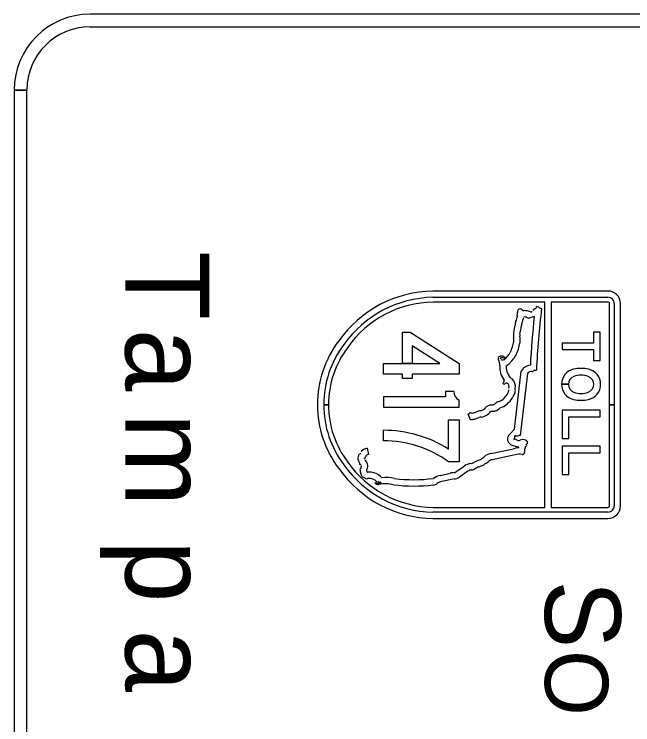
# Model space of a CAD drawing. Extents: x -830008.4 to -829992.7, y 1290284.1 to 1290294.4.
# Drawn here: x -830004.537 to -830004.047, y 1290288.025 to 1290288.587 of the extents above; entities that cross this region are included whole.
import ezdxf

# ---------------------------------------------------------------- set-up
doc = ezdxf.new("R2010")
doc.units = 0
doc.layers.add('SheetBorder_dp', color=7, linetype='Continuous')

msp = doc.modelspace()

# ---------------------------------------------------------------- linework, layer by layer
at = {"layer": 'SheetBorder_dp'}
for p, q in [((-830003.816909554, 1290288.587291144), (-830004.476909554, 1290288.587291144)), ((-830004.476909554, 1290288.577291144), (-830003.816909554, 1290288.577291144)), ((-830004.536909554, 1290288.527291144), (-830004.526909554, 1290288.527291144)), ((-830004.536909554, 1290288.527191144), (-830004.536909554, 1290287.717291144)), ((-830004.526909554, 1290288.5271911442), (-830004.536909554, 1290288.527191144)), ((-830004.526909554, 1290287.717291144), (-830004.526909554, 1290288.5271911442)), ((-830004.0981922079, 1290288.2943725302), (-830004.1035956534, 1290288.2943725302)), ((-830004.1035956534, 1290288.29437103), (-830004.0981922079, 1290288.29437103)), ((-830004.2446846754, 1290288.2497011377), (-830004.2446846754, 1290288.2579751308)), ((-830004.1930847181, 1290288.2430990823), (-830004.1930847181, 1290288.2430990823))]:
    msp.add_line(p, q, dxfattribs=at)
for points in [[(-830004.0669087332, 1290288.3682224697), (-830004.2054374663, 1290288.3682224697)], [(-830004.205393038, 1290288.3632224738), (-830004.0669087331, 1290288.3632224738)], [(-830004.2053588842, 1290288.1969726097), (-830004.1169086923, 1290288.1969726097), (-830004.1169086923, 1290288.3594724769), (-830004.2053588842, 1290288.3594724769)], [(-830004.0669087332, 1290288.3594724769), (-830004.1119086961, 1290288.3594724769), (-830004.1119086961, 1290288.19697261), (-830004.0669087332, 1290288.19697261)], [(-830004.0619087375, 1290288.3582224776), (-830004.0619087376, 1290288.2782225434), (-830004.0656587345, 1290288.2782225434), (-830004.0656587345, 1290288.3582224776)], [(-830004.0569087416, 1290288.198222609), (-830004.0569087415, 1290288.3582224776)], [(-830004.1261738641, 1290288.3530989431), (-830004.1257116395, 1290288.3532741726)], [(-830004.1387743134, 1290288.34870282), (-830004.138744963, 1290288.348874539)], [(-830004.1385513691, 1290288.348487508), (-830004.1387164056, 1290288.3485801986)], [(-830004.125191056, 1290288.3481242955), (-830004.1291381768, 1290288.346627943)], [(-830004.1448537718, 1290288.2546439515), (-830004.1408525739, 1290288.2590014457), (-830004.1355260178, 1290288.3048247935)], [(-830004.1307013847, 1290288.3030265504), (-830004.136407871, 1290288.2539347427)], [(-830004.188884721, 1290288.2886301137), (-830004.195484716, 1290288.2886301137), (-830004.1954847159, 1290288.2844931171)], [(-830004.1954847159, 1290288.2844931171), (-830004.2446846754, 1290288.2844931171), (-830004.2446846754, 1290288.2762191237), (-830004.1846847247, 1290288.276219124), (-830004.1846847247, 1290288.281833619)], [(-830004.2881585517, 1290288.2782225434), (-830004.2919085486, 1290288.2782225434)], [(-830004.2919085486, 1290288.2782205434), (-830004.2881585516, 1290288.2782205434)], [(-830004.2919085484, 1290288.2782205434), (-830004.2919085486, 1290288.2782205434)], [(-830004.0656587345, 1290288.1982226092), (-830004.0656587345, 1290288.2782205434), (-830004.0619087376, 1290288.2782205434), (-830004.0619087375, 1290288.198222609)], [(-830004.1930847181, 1290288.2430990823), (-830004.1930847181, 1290288.2661687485), (-830004.1846847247, 1290288.2661687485), (-830004.1846847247, 1290288.2330727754), (-830004.1930847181, 1290288.2330727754)], [(-830004.1757909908, 1290288.2661882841), (-830004.1775703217, 1290288.2708609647)], [(-830004.1409836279, 1290288.251466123), (-830004.141267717, 1290288.2511567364)], [(-830004.2575626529, 1290288.24375316), (-830004.2565490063, 1290288.2388569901)], [(-830004.1595911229, 1290288.2396098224), (-830004.14163251, 1290288.2434177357)], [(-830004.137820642, 1290288.2440571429), (-830004.1375218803, 1290288.2449362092)], [(-830004.1324797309, 1290288.2442337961), (-830004.1330139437, 1290288.2426619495)], [(-830004.1404133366, 1290288.2385650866), (-830004.1586556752, 1290288.2346970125)], [(-830004.174686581, 1290288.2317725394), (-830004.1711591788, 1290288.2336529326)], [(-830004.1872336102, 1290288.2250885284), (-830004.1807183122, 1290288.2295878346)], [(-830004.1692456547, 1290288.2290069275), (-830004.1725016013, 1290288.2272712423)], [(-830004.259800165, 1290288.2204873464), (-830004.2609410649, 1290288.2208415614)], [(-830004.1994168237, 1290288.2223282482), (-830004.1919079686, 1290288.2240285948)], [(-830004.1776866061, 1290288.2256050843), (-830004.1844265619, 1290288.220950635)], [(-830004.1907742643, 1290288.2191587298), (-830004.1985112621, 1290288.2174067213)], [(-830004.0669087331, 1290288.193222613), (-830004.205393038, 1290288.193222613)], [(-830004.2054374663, 1290288.1882226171), (-830004.0669087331, 1290288.1882226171)]]:
    msp.add_lwpolyline(points, dxfattribs=at)
for points in [[(-830004.2296432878, 1290288.335617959), (-830004.2234668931, 1290288.335617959), (-830004.1846847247, 1290288.310795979), (-830004.1846847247, 1290288.3025219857), (-830004.221843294, 1290288.302521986), (-830004.221843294, 1290288.2989759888), (-830004.2296432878, 1290288.2989759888), (-830004.2296432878, 1290288.3025219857), (-830004.2446846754, 1290288.3025219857), (-830004.2446846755, 1290288.310795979), (-830004.2001014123, 1290288.310795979), (-830004.221843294, 1290288.3247113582), (-830004.2218432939, 1290288.310798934), (-830004.2296432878, 1290288.310798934)], [(-830004.0784087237, 1290288.3356224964), (-830004.0784087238, 1290288.3270725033), (-830004.1031587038, 1290288.3270725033), (-830004.1031587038, 1290288.3218225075), (-830004.0784087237, 1290288.3218225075), (-830004.0784087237, 1290288.3132725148), (-830004.0731587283, 1290288.3132725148), (-830004.0731587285, 1290288.3356224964)], [(-830004.1031587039, 1290288.2516225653), (-830004.0979087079, 1290288.2516225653), (-830004.0979087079, 1290288.2687225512), (-830004.0731587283, 1290288.2687225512), (-830004.0731587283, 1290288.273972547), (-830004.1031587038, 1290288.273972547)], [(-830004.1031587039, 1290288.2229725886), (-830004.0979087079, 1290288.2229725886), (-830004.0979087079, 1290288.2400725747), (-830004.0731587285, 1290288.2400725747), (-830004.0731587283, 1290288.2453225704), (-830004.1031587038, 1290288.2453225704)]]:
    msp.add_lwpolyline(points, close=True, dxfattribs=at)
for centre, radius, start, end in [((-830004.476909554, 1290288.527291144), 0.05999999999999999, 90.00000000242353, 180.00000000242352), ((-830004.476909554, 1290288.527291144), 0.05000000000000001, 90.00000000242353, 180.00000000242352), ((-830004.2038046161, 1290288.275081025), 0.09315575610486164, 91.00434193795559, 144.7824347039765), ((-830004.0669087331, 1290288.3582224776), 0.009999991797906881, 2.423533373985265e-09, 90.00000000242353), ((-830004.2038046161, 1290288.275081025), 0.08815576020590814, 91.03243189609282, 144.83740042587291), ((-830004.0669087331, 1290288.3582224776), 0.004999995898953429, 2.4235191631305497e-09, 90.00000000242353), ((-830004.2038046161, 1290288.275081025), 0.08440576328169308, 91.0551178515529, 144.883032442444), ((-830004.1240072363, 1290288.3554398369), 0.0005142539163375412, 298.4069525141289, 10.835103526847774), ((-830004.1231717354, 1290288.3556065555), 0.0003377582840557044, 75.52908349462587, 191.96938409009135), ((-830004.150207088, 1290288.2872858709), 0.07381051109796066, 67.16009206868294, 68.44316308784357), ((-830004.0669087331, 1290288.3582224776), 0.0012499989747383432, 2.4230217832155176e-09, 90.00000000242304), ((-830004.1494486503, 1290288.3514472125), 0.011008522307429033, 346.4850910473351, 358.21970391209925), ((-830004.1327886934, 1290288.3513882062), 0.0056638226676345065, 163.2595638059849, 182.86400577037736), ((-830004.136357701, 1290288.351879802), 0.0021770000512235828, 39.09543145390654, 148.42860737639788), ((-830004.1337250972, 1290288.3538688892), 0.0011265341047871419, 213.16301982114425, 279.1931240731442), ((-830004.134058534, 1290288.334774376), 0.017989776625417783, 69.2674504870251, 88.3645978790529), ((-830004.1275632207, 1290288.352184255), 0.0005986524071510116, 257.7695425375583, 302.1923495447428), ((-830004.1279048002, 1290288.3528732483), 0.0013659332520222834, 298.91861737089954, 349.1899173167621), ((-830004.1260337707, 1290288.352587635), 0.0005301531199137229, 105.32244340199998, 176.8180848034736), ((-830004.1257972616, 1290288.3536258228), 0.00036192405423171, 283.6844802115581, 22.75102928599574), ((-830004.1252127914, 1290288.3538480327), 0.0002638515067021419, 104.46933041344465, 198.16203331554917), ((-830004.1291469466, 1290288.3624800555), 0.009226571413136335, 294.78716688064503, 305.70207615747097), ((-830003.550934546, 1290288.2820833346), 0.5730414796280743, 172.74340527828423, 177.64053368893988), ((-830004.118862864, 1290288.3590295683), 0.004593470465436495, 234.090301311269, 263.45802429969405), ((-830004.0454778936, 1290288.3126107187), 0.09965940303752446, 158.96382008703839, 161.50316928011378), ((-830004.1386791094, 1290288.348672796), 9.9826512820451e-05, 162.496701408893, 248.06130225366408), ((-830004.1385744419, 1290288.3484081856), 8.261021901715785e-05, 343.1200005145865, 73.7815449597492), ((-830004.0454778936, 1290288.3126107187), 0.09465940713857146, 158.9395609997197, 161.3538881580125), ((-830004.1385744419, 1290288.3484081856), 0.005082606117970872, 339.48312628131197, 352.50601186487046), ((-830004.1337250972, 1290288.3538688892), 0.006126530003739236, 271.7757633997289, 272.7092640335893), ((-830004.134058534, 1290288.334774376), 0.01298978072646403, 77.51121985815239, 87.25088211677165), ((-830004.1279048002, 1290288.3528732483), 0.0063659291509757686, 238.30424406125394, 258.8284940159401), ((-830003.550934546, 1290288.2820833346), 0.5780414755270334, 173.43965958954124, 177.2795063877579), ((-830004.2198288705, 1290288.352123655), 0.08016743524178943, 347.9815123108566, 352.25032233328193), ((-830004.1247112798, 1290288.340621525), 0.015697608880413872, 166.71827368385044, 177.47368236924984), ((-830004.2131072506, 1290288.3510964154), 0.0783691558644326, 347.42098246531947, 352.51703163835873), ((-830004.1247112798, 1290288.340621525), 0.010697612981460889, 167.8371768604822, 178.56038546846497), ((-830004.133587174, 1290288.333143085), 0.008158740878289, 163.71730815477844, 193.3081791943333), ((-830004.133587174, 1290288.333143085), 0.0031587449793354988, 163.71730815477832, 194.09444291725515), ((-830004.2131586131, 1290288.2782225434), 0.08374993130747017, 142.84750742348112, 179.9993266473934), ((-830004.1497002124, 1290288.3295572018), 0.008349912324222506, 344.30322825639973, 11.802168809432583), ((-830004.1497002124, 1290288.3295572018), 0.01334990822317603, 345.2933259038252, 12.180223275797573), ((-830004.2131586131, 1290288.2782225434), 0.0787499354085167, 142.78617292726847, 180.00000000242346), ((-830004.2131586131, 1290288.2782225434), 0.07499993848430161, 142.73495458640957, 180.00000000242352), ((-830004.169564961, 1290288.3326148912), 0.02840527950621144, 330.4722802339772, 349.2120997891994), ((-830004.169564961, 1290288.3326148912), 0.03340527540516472, 330.1681482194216, 348.87275100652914), ((-830004.1530039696, 1290288.3153763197), 0.000901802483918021, 108.32673284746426, 189.0854984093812), ((-830004.1511357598, 1290288.3121874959), 0.004581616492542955, 57.31174888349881, 118.0117489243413), ((-830004.1566254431, 1290288.3264806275), 0.01416135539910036, 312.410764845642, 326.26217754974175), ((-830004.1383939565, 1290288.3178459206), 0.015719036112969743, 189.56510050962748, 202.43401243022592), ((-830004.1564028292, 1290288.3100726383), 0.00390587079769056, 349.75666267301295, 27.02253734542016), ((-830004.1514036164, 1290288.3146474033), 0.0006510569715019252, 120.7488524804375, 235.01068498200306), ((-830004.1502268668, 1290288.3180414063), 0.004222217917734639, 248.461594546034, 274.2264195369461), ((-830004.1505274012, 1290288.3115154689), 0.0038844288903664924, 74.6263603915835, 108.13545261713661), ((-830004.1496703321, 1290288.3154151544), 0.0016033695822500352, 261.19737803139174, 323.4243709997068), ((-830004.149169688, 1290288.3158976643), 0.0007162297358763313, 242.75361409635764, 336.469149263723), ((-830004.1486821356, 1290288.3157949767), 0.0002493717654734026, 312.70176638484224, 85.22491620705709), ((-830004.1334120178, 1290288.303275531), 0.018687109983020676, 136.97994108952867, 143.23758320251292), ((-830004.1503473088, 1290288.3160387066), 0.0075193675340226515, 291.67644084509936, 322.5951392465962), ((-830004.1334120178, 1290288.303275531), 0.01368711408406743, 137.6878246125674, 143.2173430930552), ((-830004.1566254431, 1290288.3264806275), 0.019161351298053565, 313.09802819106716, 326.8309060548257), ((-830004.1352930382, 1290288.308246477), 0.017303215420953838, 176.25033295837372, 217.78592799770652), ((-830004.1352930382, 1290288.308246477), 0.012303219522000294, 176.2503329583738, 217.7859279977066), ((-830004.127333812, 1290288.3001287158), 0.009442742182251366, 96.02257115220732, 150.17705715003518), ((-830004.1268230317, 1290288.3057072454), 0.0011761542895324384, 256.0840041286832, 320.7997150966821), ((-830004.1244722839, 1290288.3029491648), 0.002476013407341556, 89.3658460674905, 125.54177339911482), ((-830004.1244963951, 1290288.3075714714), 0.002147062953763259, 271.37486247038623, 297.9457993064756), ((-830004.0915219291, 1290288.29454494), 0.012074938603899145, 102.4981805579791, 180.81811666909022), ((-830004.0880125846, 1290288.277329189), 0.029643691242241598, 90.28244722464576, 101.91938333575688), ((-830004.0883048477, 1290288.277329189), 0.029643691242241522, 78.08061666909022, 89.71755278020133), ((-830004.0847955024, 1290288.29454494), 0.012074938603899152, 359.1818833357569, 77.501819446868), ((-830004.1405214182, 1290288.3031962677), 0.0051376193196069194, 208.96641707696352, 243.7554146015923), ((-830004.127333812, 1290288.3001287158), 0.004442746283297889, 87.05939003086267, 139.28762858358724), ((-830004.0913706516, 1290288.2943182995), 0.006821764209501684, 111.70520555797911, 179.54451111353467), ((-830004.0881977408, 1290288.2832171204), 0.01834585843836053, 89.87812222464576, 108.08747222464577), ((-830004.0881196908, 1290288.2832171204), 0.018345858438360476, 71.91253055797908, 90.12188055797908), ((-830004.0849467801, 1290288.2943182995), 0.006821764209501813, 0.4554861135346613, 68.29479166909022), ((-830004.1496472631, 1290288.2951638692), 0.00045159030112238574, 138.4958369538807, 251.35547825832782), ((-830004.1485266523, 1290288.294595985), 0.0016970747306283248, 122.41171091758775, 149.27204594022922), ((-830004.1491500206, 1290288.2959203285), 0.0013469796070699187, 241.55366301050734, 319.3578507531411), ((-830004.1502933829, 1290288.2971529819), 0.0014137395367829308, 307.31988608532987, 20.348141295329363), ((-830004.1473254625, 1290288.2942638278), 0.0011185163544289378, 62.17967687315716, 135.8444191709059), ((-830004.1478292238, 1290288.2927200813), 0.002732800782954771, 337.67396999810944, 67.95366907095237), ((-830004.1478292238, 1290288.2927200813), 0.007732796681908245, 346.95366894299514, 49.36461062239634), ((-830004.091521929, 1290288.2942001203), 0.012074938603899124, 179.1890027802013, 257.50181944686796), ((-830004.0913706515, 1290288.2944267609), 0.006821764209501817, 180.46808611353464, 248.29479444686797), ((-830004.0849467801, 1290288.2944267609), 0.00682176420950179, 291.70520555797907, 359.54451111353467), ((-830004.0847955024, 1290288.2942001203), 0.01207493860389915, 282.4981805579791, 0.8181166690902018), ((-830004.1598542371, 1290288.2943221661), 0.015352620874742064, 306.24805817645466, 342.4314901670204), ((-830004.1598542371, 1290288.2943221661), 0.02035261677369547, 305.5557055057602, 342.5764176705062), ((-830004.1446703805, 1290288.2909548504), 0.0009626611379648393, 130.94785174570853, 209.13238131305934), ((-830004.1459191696, 1290288.2898831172), 0.0007280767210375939, 344.45855160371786, 55.926714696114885), ((-830004.1459191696, 1290288.2898831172), 0.005728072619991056, 343.20405950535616, 10.983730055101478), ((-830004.088197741, 1290288.30552794), 0.018345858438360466, 251.9125305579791, 270.1218805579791), ((-830004.0881196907, 1290288.30552794), 0.01834585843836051, 269.8781222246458, 288.0874722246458), ((-830004.2131586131, 1290288.2782225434), 0.08374993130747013, 180.00067335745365, 217.1524925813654), ((-830004.2131586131, 1290288.2782225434), 0.0787499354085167, 180.0014551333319, 217.21382707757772), ((-830004.2131586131, 1290288.2782225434), 0.07499993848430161, 180.00152788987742, 217.2650454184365), ((-830004.160639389, 1290288.2740730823), 0.0035387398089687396, 108.80938420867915, 147.92252183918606), ((-830004.1570363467, 1290288.261434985), 0.01667684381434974, 95.83401018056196, 106.52696873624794), ((-830004.1587530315, 1290288.2818232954), 0.0037979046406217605, 270.32491508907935, 313.66161233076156), ((-830004.151636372, 1290288.2748014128), 0.006202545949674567, 115.82198903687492, 136.43866082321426), ((-830004.1588723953, 1290288.2956158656), 0.01589183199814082, 286.5782858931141, 300.62635306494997), ((-830004.1588723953, 1290288.2956158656), 0.020891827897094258, 288.18436485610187, 301.2980191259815), ((-830004.0880125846, 1290288.3114158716), 0.029643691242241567, 258.08061666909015, 269.71755278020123), ((-830004.0883048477, 1290288.3114158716), 0.029643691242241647, 270.28244722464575, 281.91938333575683), ((-830004.1787230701, 1290288.273888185), 0.003239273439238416, 290.84655294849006, 319.44354465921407), ((-830004.1756458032, 1290288.270418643), 0.0014961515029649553, 67.22849549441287, 114.32059462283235), ((-830004.1741864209, 1290288.2738800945), 0.0022603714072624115, 247.0801304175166, 290.7155326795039), ((-830004.1772339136, 1290288.2856712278), 0.014427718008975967, 285.4646039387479, 295.40257351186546), ((-830004.1673507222, 1290288.2651480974), 0.008351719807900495, 91.67742197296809, 116.25136942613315), ((-830004.168737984, 1290288.2797535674), 0.00636082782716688, 280.3499605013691, 323.30234002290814), ((-830004.168737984, 1290288.2797535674), 0.01136082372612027, 277.75508185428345, 322.19232630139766), ((-830004.1570363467, 1290288.261434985), 0.011676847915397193, 96.67124163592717, 103.49925455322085), ((-830004.1587530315, 1290288.2818232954), 0.008797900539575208, 272.3461760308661, 314.88601300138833), ((-830004.151636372, 1290288.2748014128), 0.0012025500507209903, 126.55264334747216, 139.03031646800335), ((-830004.1787230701, 1290288.273888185), 0.008239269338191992, 290.8465529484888, 298.46996335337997), ((-830004.1741864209, 1290288.2738800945), 0.0072603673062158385, 265.18832348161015, 288.5199915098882), ((-830004.1772339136, 1290288.2856712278), 0.019427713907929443, 285.99582599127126, 295.54388377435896), ((-830004.1673507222, 1290288.2651480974), 0.0033517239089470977, 87.50761993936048, 116.69852875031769), ((-830004.1412061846, 1290288.251067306), 0.0051085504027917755, 135.56262045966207, 237.29796913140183), ((-830004.1412061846, 1290288.251067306), 0.00010855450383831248, 124.5297148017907, 233.1329502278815), ((-830004.14093914, 1290288.2515380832), 0.0006490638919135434, 239.21798511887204, 266.8710685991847), ((-830004.1414124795, 1290288.2517948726), 0.0005403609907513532, 322.52689923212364, 0.6169914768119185), ((-830004.1418736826, 1290288.2444274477), 0.006524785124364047, 62.38532883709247, 82.07944276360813), ((-830004.13229883, 1290288.2523730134), 0.008592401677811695, 173.5112557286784, 183.81918171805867), ((-830004.140354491, 1290288.2532705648), 0.00048726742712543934, 63.69433276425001, 171.32917886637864), ((-830004.1396910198, 1290288.2550933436), 0.0014564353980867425, 252.10457642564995, 275.52582079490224), ((-830004.1398432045, 1290288.2693869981), 0.015746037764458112, 271.0641447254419, 278.90292636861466), ((-830004.1374938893, 1290288.253439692), 0.003503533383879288, 247.24022841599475, 287.19148449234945), ((-830004.136744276, 1290288.2523205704), 0.0016488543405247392, 78.22765468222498, 113.67363847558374), ((-830004.1340271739, 1290288.244242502), 0.006335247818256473, 67.74858133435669, 112.5665335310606), ((-830004.131225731, 1290288.249831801), 0.0004869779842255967, 145.73628075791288, 266.03288678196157), ((-830004.1317159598, 1290288.247950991), 0.0014678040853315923, 25.31561269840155, 71.87839786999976), ((-830004.2556492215, 1290288.234510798), 0.009438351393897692, 101.69661581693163, 132.0003516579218), ((-830004.14093914, 1290288.2515380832), 0.005649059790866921, 237.5985007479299, 263.226429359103), ((-830004.1368672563, 1290288.2266914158), 0.017391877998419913, 93.14240769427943, 105.90201518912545), ((-830004.1418736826, 1290288.2444274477), 0.00152478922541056, 58.612417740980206, 79.8671016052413), ((-830004.1374938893, 1290288.253439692), 0.008503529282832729, 245.06021293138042, 269.8113984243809), ((-830004.1370197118, 1290288.245093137), 0.004620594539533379, 349.28168725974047, 354.9051382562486), ((-830004.1338841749, 1290288.2470127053), 0.002753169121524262, 302.19270369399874, 330.49478773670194), ((-830004.131010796, 1290288.2464863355), 0.0005585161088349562, 157.0069622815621, 214.09452369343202), ((-830004.1264012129, 1290288.2435812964), 0.006000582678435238, 133.56431047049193, 148.63528521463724), ((-830004.1318894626, 1290288.2459266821), 0.00048371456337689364, 326.0813076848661, 30.646894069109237), ((-830004.1309590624, 1290288.2483667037), 0.0006080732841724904, 314.00455558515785, 20.39690129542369), ((-830004.2597941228, 1290288.235984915), 0.005082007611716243, 153.32332099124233, 203.7616015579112), ((-830004.2631944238, 1290288.237952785), 0.001183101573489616, 101.34797747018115, 164.6228978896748), ((-830004.2644986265, 1290288.2408045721), 0.002002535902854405, 302.3456172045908, 343.61589590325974), ((-830004.2598918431, 1290288.2397480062), 0.002730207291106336, 139.39815901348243, 169.62463341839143), ((-830004.2644986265, 1290288.2408045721), 0.007002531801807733, 312.69591869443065, 339.04967932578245), ((-830004.2556492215, 1290288.234510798), 0.004438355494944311, 101.6966158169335, 121.36036735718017), ((-830004.1577784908, 1290288.2292429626), 0.010524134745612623, 99.91783571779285, 132.33551436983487), ((-830004.1368672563, 1290288.2266914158), 0.01239188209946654, 80.7154347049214, 106.6282936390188), ((-830004.1344755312, 1290288.2404860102), 0.0016135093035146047, 255.92308929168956, 10.34417786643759), ((-830004.1294601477, 1290288.2419514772), 0.0036241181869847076, 168.69451550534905, 198.93056612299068), ((-830004.2038046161, 1290288.2813640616), 0.08440576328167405, 215.1169675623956, 268.9448821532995), ((-830004.2205653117, 1290288.250731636), 0.04698413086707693, 200.94360574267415, 204.61565768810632), ((-830004.2205653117, 1290288.250731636), 0.04198413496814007, 201.04078519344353, 202.5202058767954), ((-830004.2630724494, 1290288.2298853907), 0.0060486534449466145, 330.4014101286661, 51.992782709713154), ((-830004.1757726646, 1290288.2498300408), 0.01682210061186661, 285.91740885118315, 310.4167178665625), ((-830004.1757726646, 1290288.2498300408), 0.021822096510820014, 287.40361120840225, 310.6854632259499), ((-830004.1577784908, 1290288.2292429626), 0.005524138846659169, 99.13673946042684, 133.0108286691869), ((-830004.2038046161, 1290288.2813640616), 0.0931557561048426, 215.21756530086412, 268.99565806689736), ((-830004.2038046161, 1290288.2813640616), 0.08815576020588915, 215.1625995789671, 268.96756810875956), ((-830004.262956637, 1290288.2312646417), 0.0003391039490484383, 197.73039721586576, 257.8776837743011), ((-830004.2630724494, 1290288.2298853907), 0.0010486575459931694, 329.3592018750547, 87.56239300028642), ((-830004.2613457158, 1290288.2270920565), 0.0016655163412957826, 170.34138513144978, 189.65861487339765), ((-830004.2540039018, 1290288.224820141), 0.009338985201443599, 150.97778255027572, 164.14560497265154), ((-830004.3095928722, 1290288.2169732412), 0.04763257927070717, 7.768957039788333, 11.921319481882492), ((-830004.2540039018, 1290288.224820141), 0.0043389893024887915, 151.3901188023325, 153.29598296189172), ((-830004.3095928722, 1290288.2169732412), 0.052632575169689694, 8.731277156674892, 10.727310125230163), ((-830004.174998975, 1290288.222538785), 0.00907743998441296, 92.84391301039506, 129.05458954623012), ((-830004.174998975, 1290288.222538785), 0.004077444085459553, 92.8834470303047, 131.2347684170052), ((-830004.175560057, 1290288.2339297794), 0.0023273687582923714, 272.72632054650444, 292.0432456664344), ((-830004.175560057, 1290288.2339297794), 0.007327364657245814, 272.784563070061, 294.6706660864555), ((-830004.253845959, 1290288.2255820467), 0.008822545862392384, 194.2378971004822, 209.9305928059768), ((-830004.2606738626, 1290288.221893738), 0.0010855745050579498, 221.10528333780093, 255.75081490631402), ((-830004.2613706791, 1290288.2171963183), 0.008646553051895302, 61.93445424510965, 63.92600877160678), ((-830004.2556880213, 1290288.2153464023), 0.009616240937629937, 81.6034085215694, 99.66603998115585), ((-830004.2566743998, 1290288.2103024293), 0.014752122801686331, 49.135427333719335, 80.67409304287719), ((-830004.2506342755, 1290288.216865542), 0.005843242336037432, 37.779951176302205, 51.82137985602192), ((-830004.243102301, 1290288.1869314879), 0.033640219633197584, 77.48506247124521, 94.96874020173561), ((-830004.1976320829, 1290288.2105981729), 0.01186507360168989, 98.65125061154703, 128.6551561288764), ((-830004.1874663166, 1290288.205387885), 0.019162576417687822, 94.56777406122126, 103.40235126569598), ((-830004.1892613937, 1290288.2281613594), 0.003681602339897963, 274.19014254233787, 303.42110564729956), ((-830004.1892613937, 1290288.2281613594), 0.008681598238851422, 274.3295736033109, 303.842076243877), ((-830004.2613706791, 1290288.2171963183), 0.0036465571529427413, 47.41639513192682, 64.489020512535), ((-830004.2578813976, 1290288.2214594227), 0.001880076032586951, 237.07918702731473, 291.80066608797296), ((-830004.2556880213, 1290288.2153464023), 0.004616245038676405, 82.06654542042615, 108.89835051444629), ((-830004.2566743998, 1290288.2103024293), 0.009752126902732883, 48.195915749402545, 80.41682921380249), ((-830004.2508991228, 1290288.2161899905), 0.00036294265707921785, 106.47272706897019, 245.0578696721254), ((-830004.2486390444, 1290288.2195552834), 0.0044126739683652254, 236.84787044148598, 265.1084461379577), ((-830004.250689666, 1290288.216040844), 0.0005871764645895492, 44.20762038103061, 122.14003043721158), ((-830004.2490800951, 1290288.218286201), 0.002187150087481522, 237.07914318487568, 270.54781027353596), ((-830004.2506342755, 1290288.216865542), 0.0008432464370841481, 30.732677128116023, 56.89960743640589), ((-830004.249363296, 1290288.217806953), 0.0007475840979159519, 223.06631752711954, 271.03560150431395), ((-830004.248967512, 1290288.2130295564), 0.004048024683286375, 80.3513981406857, 95.41876184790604), ((-830004.2496373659, 1290288.209287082), 0.006836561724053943, 69.77478980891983, 85.14858343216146), ((-830004.2484490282, 1290288.2183144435), 0.0032061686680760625, 259.8268456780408, 275.11891385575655), ((-830004.2445877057, 1290288.270222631), 0.05333090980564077, 266.0202890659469, 267.26569028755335), ((-830004.243102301, 1290288.1869314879), 0.028640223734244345, 77.00314932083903, 100.17747131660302), ((-830004.247143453, 1290288.21646757), 0.000776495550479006, 260.32948006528, 287.13639500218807), ((-830004.2473017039, 1290288.215596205), 0.0013668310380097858, 37.658419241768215, 82.86083607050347), ((-830004.2479940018, 1290288.2182346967), 0.002731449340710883, 293.2755336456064, 310.082534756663), ((-830004.2463984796, 1290288.216297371), 0.00022342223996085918, 316.9365276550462, 36.821668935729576), ((-830004.2208068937, 1290288.347307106), 0.12841446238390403, 263.2894160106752, 277.0511251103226), ((-830004.2049498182, 1290288.2194047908), 0.004586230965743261, 268.16970798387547, 310.7248464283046), ((-830004.1976320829, 1290288.2105981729), 0.006865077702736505, 97.357815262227, 129.05608381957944), ((-830004.1874663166, 1290288.205387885), 0.014162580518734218, 94.6156238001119, 103.50731900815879), ((-830004.2208068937, 1290288.347307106), 0.1334144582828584, 263.1751342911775, 276.7627173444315), ((-830004.0669087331, 1290288.1982226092), 0.00999999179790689, 270.0000000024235, 2.423533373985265e-09), ((-830004.0669087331, 1290288.1982226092), 0.0012499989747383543, 270.0000000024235, 2.42354758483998e-09), ((-830004.0669087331, 1290288.1982226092), 0.004999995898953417, 270.00000000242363, 2.4236612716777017e-09)]:
    msp.add_arc(centre, radius, start, end, dxfattribs=at)
for centre, major_axis, ratio, start_param, end_param in [((-830004.1811168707, 1290288.2886301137), (0.007767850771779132, 3.2856949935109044e-13), 0.9849999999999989, 3.141592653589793, 4.235170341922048), ((-830004.2446846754, 1290288.1637108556), (0.09569992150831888, 4.0479762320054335e-12), 0.984999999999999, 1.001327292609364, 1.5707963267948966), ((-830004.2446846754, 1290288.1637108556), (0.08729992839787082, 3.6926679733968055e-12), 0.9849999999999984, 0.938417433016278, 1.570796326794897)]:
    msp.add_ellipse(centre, major_axis=major_axis, ratio=ratio, start_param=start_param, end_param=end_param, dxfattribs=at)

# ---------------------------------------------------------------- texts
for s, height, p in [('T', 0.06650000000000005, (-830004.4489099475, 1290288.3997165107)), ('a', 0.06650000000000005, (-830004.4489099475, 1290288.3383370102)), ('m', 0.06650000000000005, (-830004.4489099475, 1290288.2717040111)), ('p', 0.06650000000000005, (-830004.4489099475, 1290288.1710895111)), ('S', 0.06000000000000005, (-830004.1167386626, 1290288.1390542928)), ('a', 0.06650000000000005, (-830004.4489099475, 1290288.1002670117)), ('O', 0.05000000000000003, (-830004.1167386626, 1290288.0840142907))]:
    msp.add_text(s, height=height, rotation=270.00000000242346, dxfattribs=at).set_placement(p)

doc.saveas('drawing.dxf')
